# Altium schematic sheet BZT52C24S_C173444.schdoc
size 127 x 101 mm
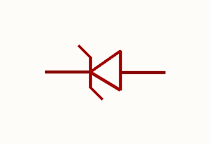
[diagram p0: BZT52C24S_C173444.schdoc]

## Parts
D?  bzt52c24s_c173444  [SOD-323_L1.8-W1.3-LS2.5-RD]  (value not drawn)

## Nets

Not connected (* = marked no-connect by the designer): D? 1 2

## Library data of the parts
D? = bzt52c24s_c173444: 二极管配置:1个独立式;稳压值(标称值):24V;稳压值(范围):22.8V~25.6V;耗散功率(Pd):200mW;; Manufacturer: MDD(辰达半导体); AddInBom: yes; ModelId: db63db13d9e342eb939127d413d6200b; ModelTransform: 104.3305,51.181,0,0,0,0,0,-0.004,0; Diode Configuration: 1个独立式; Zener Voltage(Nom): 24V; Reverse Leakage Current (Ir): 100nA; Pd - Power Dissipation: 200mW; Impedance(Zzt): 60Ω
